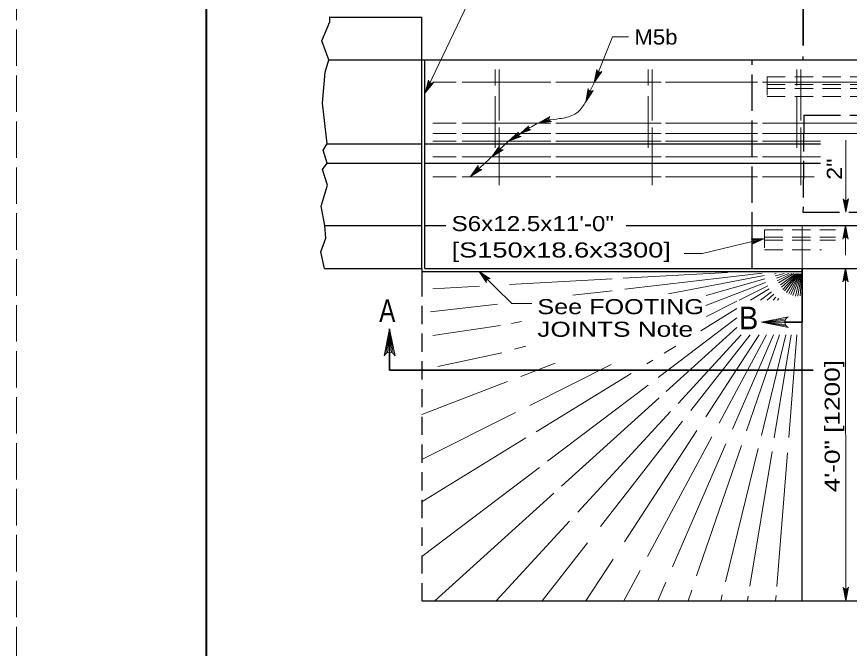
# Model space of a CAD drawing. Extents: x -1431.2 to -1397.2, y -1045.1 to -1001.1.
# Drawn here: x -1431.25 to -1422.47, y -1011.95 to -1005.3 of the extents above; entities that cross this region are included whole.
import ezdxf
from ezdxf.enums import TextEntityAlignment as Align

# ---------------------------------------------------------------- set-up
doc = ezdxf.new("R2010")
doc.units = 0
doc.header["$LTSCALE"] = 0.064
doc.linetypes.add('LONG_DASHED', pattern=[7.5, 6, -1.5])
doc.linetypes.add('MEDIUM_DASHED', pattern=[4.5, 3, -1.5])
doc.layers.add('1', color=7, linetype='Continuous', lineweight=13)

msp = doc.modelspace()

# ---------------------------------------------------------------- linework, layer by layer
at = {"layer": '1', "lineweight": 35}
for p, q in [((-1422.95608, -1005.60267), (-1422.95608, -1005.11975)), ((-1422.96592, -1007.95217), (-1422.96592, -1008.517)), ((-1423.08525, -1008.517), (-1423.15958, -1008.517)), ((-1422.96592, -1008.517), (-1423.08525, -1008.517)), ((-1427.31517, -1008.58883), (-1427.31517, -1009.0255)), ((-1422.84992, -1009.0255), (-1427.31517, -1009.0255))]:
    msp.add_line(p, q, dxfattribs=at)
at = {"layer": '1', "lineweight": 25}
for p, q in [((-1427.93092, -1005.30383), (-1426.97542, -1005.30383)), ((-1426.97542, -1007.86367), (-1426.97542, -1005.30083)), ((-1426.94317, -1007.86367), (-1426.94317, -1005.75617)), ((-1422.95608, -1005.75617), (-1422.95608, -1005.71917)), ((-1427.97375, -1006.64083), (-1426.97542, -1006.64083)), ((-1426.94317, -1006.64083), (-1422.77283, -1006.64083)), ((-1427.97375, -1006.84225), (-1426.97542, -1006.84225)), ((-1426.94317, -1006.84225), (-1422.77283, -1006.84225)), ((-1427.99758, -1007.49992), (-1426.97542, -1007.49992)), ((-1426.94317, -1007.49992), (-1426.723, -1007.49992)), ((-1424.82358, -1007.49992), (-1416.292, -1007.49992)), ((-1426.97542, -1007.95217), (-1426.97542, -1007.86367)), ((-1426.94317, -1007.95217), (-1426.94317, -1007.86367)), ((-1428.00233, -1007.95217), (-1426.97542, -1007.95217)), ((-1426.94317, -1007.95217), (-1422.96933, -1007.95242)), ((-1422.96592, -1011.455), (-1422.96592, -1007.95217)), ((-1422.96592, -1007.95217), (-1422.16017, -1007.95217)), ((-1426.97542, -1007.98392), (-1422.96933, -1007.98417)), ((-1426.97542, -1011.455), (-1410.98333, -1011.455))]:
    msp.add_line(p, q, dxfattribs=at)
at = {"layer": '1', "linetype": 'LONG_DASHED', "lineweight": 25}
for p, q in [((-1423.49433, -1007.745), (-1423.49433, -1005.75617)), ((-1422.94908, -1006.33642), (-1422.95892, -1007.36058)), ((-1423.49433, -1007.95217), (-1423.49433, -1007.745))]:
    msp.add_line(p, q, dxfattribs=at)
at = {"layer": '1'}
for p, q in [((-1426.20292, -1005.85733), (-1426.20292, -1006.02692)), ((-1426.16058, -1005.85733), (-1426.16058, -1006.39358)), ((-1424.58917, -1005.85733), (-1424.58917, -1006.02692)), ((-1424.54675, -1005.85733), (-1424.54675, -1006.39358)), ((-1423.02375, -1005.85733), (-1423.02375, -1006.02692)), ((-1422.98133, -1005.85733), (-1422.98133, -1006.39358)), ((-1425.12692, -1005.87125), (-1425.15825, -1005.99408)), ((-1425.1205, -1005.8785), (-1425.15825, -1005.99408)), ((-1425.11275, -1005.883), (-1425.15825, -1005.99408)), ((-1425.09208, -1005.88392), (-1425.15825, -1005.99408)), ((-1425.1015, -1005.88525), (-1425.15825, -1005.99408)), ((-1426.9005, -1005.98392), (-1426.94142, -1006.10392)), ((-1426.89467, -1005.99158), (-1426.94142, -1006.10392)), ((-1426.88733, -1005.99683), (-1426.94142, -1006.10392)), ((-1426.86683, -1005.99925), (-1426.94142, -1006.10392)), ((-1426.87625, -1005.99983), (-1426.94142, -1006.10392)), ((-1426.85817, -1005.99167), (-1426.61533, -1005.99167)), ((-1426.55142, -1005.99167), (-1425.61742, -1005.99167)), ((-1425.56242, -1005.99167), (-1424.45342, -1005.99167)), ((-1424.40625, -1005.99167), (-1423.43867, -1005.99167)), ((-1423.38433, -1005.99167), (-1422.26083, -1005.99167)), ((-1425.21833, -1006.07258), (-1425.24717, -1006.196)), ((-1425.21175, -1006.07967), (-1425.24717, -1006.196)), ((-1425.20392, -1006.08408), (-1425.24717, -1006.196)), ((-1425.18333, -1006.0845), (-1425.24717, -1006.196)), ((-1425.19258, -1006.086), (-1425.24717, -1006.196)), ((-1426.20292, -1006.139), (-1426.20292, -1006.68142)), ((-1424.58917, -1006.139), (-1424.58917, -1006.68142)), ((-1423.02375, -1006.139), (-1423.02375, -1006.68142)), ((-1425.63433, -1006.36725), (-1425.74867, -1006.42208)), ((-1425.63575, -1006.37683), (-1425.74867, -1006.42208)), ((-1425.63433, -1006.38567), (-1425.74867, -1006.42208)), ((-1426.85817, -1006.42175), (-1426.61533, -1006.42175)), ((-1426.55142, -1006.42175), (-1425.61742, -1006.42175)), ((-1426.16058, -1006.46925), (-1426.16058, -1007.07475)), ((-1425.85542, -1006.46475), (-1425.93567, -1006.53058)), ((-1425.85467, -1006.47267), (-1425.93567, -1006.53058)), ((-1425.62875, -1006.39575), (-1425.74867, -1006.42208)), ((-1425.62175, -1006.402), (-1425.74867, -1006.42208)), ((-1425.56242, -1006.42175), (-1424.45342, -1006.42175)), ((-1424.54675, -1006.46925), (-1424.54675, -1007.07475)), ((-1424.40625, -1006.42175), (-1423.43867, -1006.42175)), ((-1423.38433, -1006.42175), (-1422.289, -1006.42175)), ((-1422.98133, -1006.46925), (-1422.98133, -1007.07475)), ((-1426.85817, -1006.53208), (-1426.61533, -1006.53208)), ((-1426.55142, -1006.53208), (-1425.61742, -1006.53208)), ((-1425.96433, -1006.53175), (-1426.0625, -1006.612)), ((-1425.96342, -1006.54142), (-1426.0625, -1006.612)), ((-1425.95992, -1006.54967), (-1426.0625, -1006.612)), ((-1425.95217, -1006.55808), (-1426.0625, -1006.612)), ((-1425.94383, -1006.56258), (-1426.0625, -1006.612)), ((-1425.85183, -1006.47942), (-1425.93567, -1006.53058)), ((-1425.8455, -1006.48633), (-1425.93567, -1006.53058)), ((-1425.83867, -1006.48992), (-1425.93567, -1006.53058)), ((-1425.56242, -1006.53208), (-1424.45342, -1006.53208)), ((-1424.40625, -1006.53208), (-1423.43867, -1006.53208)), ((-1423.38433, -1006.53208), (-1422.289, -1006.53208)), ((-1426.85817, -1006.612), (-1426.61533, -1006.612)), ((-1426.55142, -1006.612), (-1425.61742, -1006.612)), ((-1426.0625, -1006.612), (-1426.46658, -1006.98617)), ((-1425.56242, -1006.612), (-1424.45342, -1006.612)), ((-1424.40625, -1006.612), (-1423.43867, -1006.612)), ((-1423.38433, -1006.612), (-1422.77283, -1006.612)), ((-1422.50817, -1006.60158), (-1422.50817, -1007.36058)), ((-1426.15917, -1006.67792), (-1426.23958, -1006.77592)), ((-1426.15642, -1006.68717), (-1426.23958, -1006.77592)), ((-1426.15133, -1006.69458), (-1426.23958, -1006.77592)), ((-1426.14208, -1006.70142), (-1426.23958, -1006.77592)), ((-1426.133, -1006.70417), (-1426.23958, -1006.77592)), ((-1426.85817, -1006.77592), (-1426.61533, -1006.77592)), ((-1426.55142, -1006.77592), (-1425.61742, -1006.77592)), ((-1425.56242, -1006.77592), (-1424.45342, -1006.77592)), ((-1424.40625, -1006.77592), (-1423.43867, -1006.77592)), ((-1423.38433, -1006.77592), (-1422.77283, -1006.77592)), ((-1426.3835, -1006.88525), (-1426.46392, -1006.98325)), ((-1426.38075, -1006.8945), (-1426.46392, -1006.98325)), ((-1426.37567, -1006.90192), (-1426.46392, -1006.98325)), ((-1426.36642, -1006.90867), (-1426.46392, -1006.98325)), ((-1426.35733, -1006.91142), (-1426.46392, -1006.98325)), ((-1426.85817, -1006.98883), (-1426.61533, -1006.98883)), ((-1426.55142, -1006.98883), (-1425.61742, -1006.98883)), ((-1425.56242, -1006.98883), (-1424.45342, -1006.98883)), ((-1424.40625, -1006.98883), (-1423.43867, -1006.98883)), ((-1423.38433, -1006.98883), (-1422.84142, -1006.98883)), ((-1422.52625, -1007.23125), (-1422.50817, -1007.36058)), ((-1422.51733, -1007.23558), (-1422.50817, -1007.36058)), ((-1422.48817, -1007.22967), (-1422.50817, -1007.36058)), ((-1422.49658, -1007.23467), (-1422.50817, -1007.36058)), ((-1422.50817, -1007.23692), (-1422.50817, -1007.36058)), ((-1422.96592, -1007.49992), (-1422.96592, -1007.95217)), ((-1422.53067, -1007.63075), (-1422.51067, -1007.49992)), ((-1422.52233, -1007.62583), (-1422.51067, -1007.49992)), ((-1422.51067, -1007.62358), (-1422.51067, -1007.49992)), ((-1422.50158, -1007.62492), (-1422.51067, -1007.49992)), ((-1423.49208, -1007.647), (-1423.36392, -1007.63725)), ((-1423.48558, -1007.65383), (-1423.36392, -1007.63725)), ((-1423.48225, -1007.68275), (-1423.36392, -1007.63725)), ((-1423.48083, -1007.66433), (-1423.36392, -1007.63725)), ((-1423.48008, -1007.67333), (-1423.36392, -1007.63725)), ((-1422.96592, -1007.95217), (-1422.98917, -1008.24208)), ((-1422.96592, -1007.95217), (-1422.97083, -1007.982)), ((-1422.96592, -1007.95217), (-1422.97025, -1007.96975)), ((-1422.96592, -1007.95217), (-1422.96992, -1007.96383)), ((-1422.96592, -1007.95217), (-1422.96975, -1007.96108)), ((-1422.96592, -1007.95217), (-1422.96967, -1007.95917)), ((-1422.96592, -1007.95217), (-1422.96958, -1007.95683)), ((-1422.96592, -1007.95217), (-1422.96958, -1007.95783)), ((-1422.96592, -1007.95217), (-1422.9695, -1007.95542)), ((-1422.96592, -1007.95217), (-1422.9695, -1007.95608)), ((-1422.96592, -1007.95217), (-1422.96942, -1007.95392)), ((-1422.96592, -1007.95217), (-1422.96942, -1007.95433)), ((-1422.96592, -1007.95217), (-1422.96942, -1007.95483)), ((-1422.96592, -1007.95217), (-1422.96942, -1007.9535)), ((-1422.96592, -1007.95217), (-1422.96933, -1007.95242)), ((-1422.96592, -1007.95217), (-1422.96933, -1007.95283)), ((-1422.96592, -1007.95217), (-1422.96933, -1007.95317)), ((-1422.96592, -1007.95217), (-1422.96933, -1007.95258)), ((-1422.53067, -1008.08167), (-1422.51067, -1007.95083)), ((-1422.52233, -1008.07675), (-1422.51067, -1007.95083)), ((-1422.51067, -1007.95083), (-1422.50817, -1011.455)), ((-1422.51067, -1008.0745), (-1422.51067, -1007.95083)), ((-1422.50158, -1008.07583), (-1422.51067, -1007.95083)), ((-1422.49258, -1008.08017), (-1422.51067, -1007.95083)), ((-1426.288, -1008.06875), (-1426.37292, -1007.984)), ((-1426.29442, -1008.07825), (-1426.37292, -1007.984)), ((-1426.29675, -1008.0875), (-1426.37292, -1007.984)), ((-1426.28075, -1008.06333), (-1426.37292, -1007.984)), ((-1426.27167, -1008.06017), (-1426.37292, -1007.984)), ((-1423.75267, -1007.99567), (-1424.85533, -1008.05667)), ((-1423.38983, -1008.00183), (-1424.83783, -1008.1715)), ((-1423.36767, -1008.02833), (-1424.377, -1008.21967)), ((-1423.24108, -1008.00433), (-1423.25967, -1008.00783)), ((-1423.15658, -1008.00575), (-1423.25092, -1008.03225)), ((-1423.10767, -1008.00658), (-1423.23675, -1008.05617)), ((-1423.07533, -1008.00717), (-1423.22975, -1008.08475)), ((-1423.056, -1008.0075), (-1423.21608, -1008.10558)), ((-1423.03933, -1008.00775), (-1423.19467, -1008.12525)), ((-1423.02758, -1008.00792), (-1423.18433, -1008.14975)), ((-1423.01742, -1008.00808), (-1423.17067, -1008.1745)), ((-1423.00975, -1008.00825), (-1423.15225, -1008.19017)), ((-1423.0025, -1008.00833), (-1423.13092, -1008.20567)), ((-1422.99617, -1008.0085), (-1423.1075, -1008.21583)), ((-1422.99042, -1008.00858), (-1423.08542, -1008.22708)), ((-1422.98533, -1008.00867), (-1423.06433, -1008.2385)), ((-1422.97975, -1008.00875), (-1423.03725, -1008.24308)), ((-1422.97525, -1008.00883), (-1423.01408, -1008.24383)), ((-1426.36767, -1008.14033), (-1426.86008, -1008.16758)), ((-1424.97042, -1008.06308), (-1426.05092, -1008.12283)), ((-1423.354, -1008.10108), (-1423.98425, -1008.343)), ((-1423.35958, -1008.06283), (-1423.98067, -1008.23725)), ((-1423.32892, -1008.1345), (-1423.63092, -1008.28617)), ((-1424.96892, -1008.18683), (-1425.38433, -1008.2355)), ((-1423.31417, -1008.16583), (-1423.51025, -1008.28617)), ((-1423.29125, -1008.19825), (-1423.40742, -1008.28617)), ((-1423.2655, -1008.22325), (-1423.33517, -1008.28617)), ((-1423.6545, -1008.298), (-1423.97458, -1008.45883)), ((-1423.24583, -1008.25608), (-1423.27358, -1008.28617)), ((-1423.21433, -1008.2695), (-1423.22742, -1008.28617)), ((-1426.17967, -1008.32867), (-1426.88517, -1008.41142)), ((-1423.6545, -1008.37467), (-1424.03583, -1008.60858)), ((-1423.6545, -1008.47308), (-1424.4835, -1009.10033)), ((-1423.138, -1008.4825), (-1423.39675, -1008.51875)), ((-1426.14583, -1008.55508), (-1426.86067, -1008.65817)), ((-1425.92533, -1008.51325), (-1426.03083, -1008.53325)), ((-1423.6545, -1008.575), (-1424.401, -1009.25017)), ((-1423.14675, -1008.50042), (-1423.39675, -1008.51875)), ((-1423.14942, -1008.51875), (-1423.39675, -1008.51875)), ((-1423.14483, -1008.542), (-1423.39675, -1008.51875)), ((-1423.13492, -1008.55875), (-1423.39675, -1008.51875)), ((-1427.35517, -1008.85067), (-1427.31517, -1008.58883)), ((-1427.33833, -1008.84075), (-1427.31517, -1008.58883)), ((-1427.31517, -1008.83617), (-1427.31517, -1008.58883)), ((-1427.29683, -1008.83883), (-1427.31517, -1008.58883)), ((-1427.27892, -1008.84758), (-1427.31517, -1008.58883)), ((-1423.61175, -1008.65325), (-1424.27575, -1009.37392)), ((-1423.51483, -1008.65325), (-1424.13933, -1009.45092)), ((-1423.42225, -1008.65325), (-1423.98283, -1009.51442)), ((-1423.34258, -1008.65325), (-1423.84158, -1009.58225)), ((-1423.27075, -1008.65325), (-1423.70233, -1009.64575)), ((-1423.207, -1008.65325), (-1423.554, -1009.66258)), ((-1423.13783, -1008.65325), (-1423.39758, -1009.71283)), ((-1423.08175, -1008.65325), (-1423.26083, -1009.73633)), ((-1423.02225, -1008.65325), (-1423.10883, -1009.73242)), ((-1426.13208, -1008.84158), (-1426.80608, -1008.98625)), ((-1425.87992, -1008.77075), (-1425.99967, -1008.80442)), ((-1424.30017, -1008.77075), (-1424.42067, -1008.84467)), ((-1424.54058, -1008.91825), (-1424.60542, -1008.958)), ((-1425.57033, -1008.95167), (-1425.93367, -1009.09108)), ((-1424.98042, -1008.964), (-1425.83858, -1009.39508)), ((-1424.769, -1009.05842), (-1425.77008, -1009.6725)), ((-1426.07292, -1009.1445), (-1426.97542, -1009.49083)), ((-1424.59025, -1009.18108), (-1425.65058, -1009.98325)), ((-1424.473, -1009.31525), (-1425.502, -1010.246)), ((-1425.98983, -1009.471), (-1426.97542, -1009.96608)), ((-1424.3555, -1009.46058), (-1425.33067, -1010.51908)), ((-1424.22733, -1009.56333), (-1425.09425, -1010.67058)), ((-1424.07675, -1009.65867), (-1424.84142, -1010.8335)), ((-1425.87783, -1009.73867), (-1426.97542, -1010.41208)), ((-1423.91925, -1009.72683), (-1424.59608, -1010.98667)), ((-1423.77025, -1009.802), (-1424.33233, -1011.09467)), ((-1423.60717, -1009.81717), (-1424.07967, -1011.19117)), ((-1423.43092, -1009.84858), (-1423.77533, -1011.25342)), ((-1423.285, -1009.8825), (-1423.51933, -1011.29975)), ((-1423.12208, -1009.89658), (-1423.235, -1011.30242)), ((-1425.73633, -1010.04817), (-1426.97542, -1010.98558)), ((-1425.58533, -1010.32133), (-1426.83875, -1011.455)), ((-1425.41867, -1010.61458), (-1426.19283, -1011.455)), ((-1425.23058, -1010.84467), (-1425.70842, -1011.455)), ((-1424.95933, -1011.01458), (-1425.246, -1011.455)), ((-1424.67558, -1011.13467), (-1424.84767, -1011.455)), ((-1424.40292, -1011.25683), (-1424.48908, -1011.455)), ((-1424.13158, -1011.34233), (-1424.17033, -1011.455)), ((-1422.52625, -1011.32567), (-1422.50817, -1011.455)), ((-1422.51733, -1011.33), (-1422.50817, -1011.455)), ((-1422.48817, -1011.32417), (-1422.50817, -1011.455)), ((-1422.49658, -1011.32908), (-1422.50817, -1011.455)), ((-1422.50817, -1011.33133), (-1422.50817, -1011.455)), ((-1423.80908, -1011.39117), (-1423.82475, -1011.455)), ((-1423.537, -1011.4065), (-1423.545, -1011.455)), ((-1423.24267, -1011.39817), (-1423.24725, -1011.455))]:
    msp.add_line(p, q, dxfattribs=at)
at = {"layer": '1', "linetype": 'MEDIUM_DASHED'}
for p, q in [((-1423.33717, -1005.93558), (-1423.33717, -1006.14133)), ((-1423.33717, -1005.93558), (-1416.27642, -1005.93558)), ((-1423.33717, -1006.01425), (-1416.27642, -1006.01425)), ((-1423.33717, -1006.056), (-1416.27642, -1006.056)), ((-1423.33717, -1006.14133), (-1416.27642, -1006.14133)), ((-1423.36392, -1007.5445), (-1423.36392, -1007.75642)), ((-1423.36392, -1007.5445), (-1422.6155, -1007.5445)), ((-1423.36392, -1007.6225), (-1422.6155, -1007.6225)), ((-1423.36392, -1007.65542), (-1422.6155, -1007.65542)), ((-1423.36392, -1007.75642), (-1422.76467, -1007.75642))]:
    msp.add_line(p, q, dxfattribs=at)
at = {"layer": '1', "linetype": 'LONG_DASHED'}
msp.add_lwpolyline([(-1431.24575, -1023.07983), (-1397.24575, -1023.07983), (-1397.24575, -1001.07983), (-1431.24575, -1001.07983)], close=True, dxfattribs=at)
at = {"layer": '1', "lineweight": 25}
for points in [[(-1397.74575, -1022.57983), (-1429.24575, -1022.57983), (-1429.24575, -1001.57983)], [(-1428.00233, -1007.95217), (-1428.0405, -1007.77617), (-1427.98808, -1007.63317), (-1427.99758, -1007.49992), (-1428.03567, -1007.29808), (-1427.969, -1007.07467), (-1428.02142, -1006.90933), (-1427.97375, -1006.84225), (-1428.01667, -1006.70825), (-1427.97375, -1006.64083), (-1428.02142, -1006.21233), (-1427.99283, -1005.88617), (-1427.95475, -1005.75617), (-1428.03092, -1005.5555), (-1427.94517, -1005.3545), (-1427.94517, -1005.30083), (-1427.93092, -1005.30383)], [(-1427.95475, -1005.75617), (-1426.94317, -1005.75617), (-1409.68083, -1005.75617)]]:
    msp.add_lwpolyline(points, dxfattribs=at)
at = {"layer": '1', "lineweight": 40}
msp.add_lwpolyline([(-1429.24575, -1001.57983), (-1397.74575, -1001.57983), (-1397.74575, -1022.57983), (-1429.24575, -1022.57983)], close=True, dxfattribs=at)
at = {"layer": '1'}
for points in [[(-1426.94142, -1006.10392), (-1426.15542, -1004.45958), (-1425.89817, -1004.45958)], [(-1425.16217, -1006.00292), (-1424.96517, -1005.51192), (-1424.79842, -1005.51192)], [(-1425.08, -1005.87625), (-1425.15825, -1005.99408), (-1425.13133, -1005.85525)], [(-1426.85417, -1005.99258), (-1426.94142, -1006.10392), (-1426.90367, -1005.96758)], [(-1425.17133, -1006.07667), (-1425.24717, -1006.196), (-1425.22308, -1006.05667)], [(-1425.60808, -1006.40642), (-1425.74867, -1006.42208), (-1425.62492, -1006.35358)], [(-1425.827, -1006.49083), (-1425.93567, -1006.53058), (-1425.85058, -1006.45208)], [(-1425.92958, -1006.56358), (-1426.0625, -1006.612), (-1425.95842, -1006.51625)], [(-1426.11883, -1006.70233), (-1426.23958, -1006.77592), (-1426.15642, -1006.66158)], [(-1426.34317, -1006.90958), (-1426.46392, -1006.98325), (-1426.38075, -1006.86883)], [(-1422.47958, -1007.21767), (-1422.50817, -1007.36058), (-1422.53675, -1007.21767)], [(-1422.53925, -1007.64275), (-1422.51067, -1007.49992), (-1422.48208, -1007.64275)], [(-1422.49258, -1007.62925), (-1422.51067, -1007.49992), (-1422.51067, -1007.8145)], [(-1423.36392, -1007.63725), (-1424.0185, -1007.79533), (-1424.20925, -1007.79533)], [(-1423.50525, -1007.6415), (-1423.36392, -1007.63725), (-1423.49275, -1007.69558)], [(-1422.53925, -1008.09367), (-1422.51067, -1007.95083), (-1422.48208, -1008.09367)], [(-1426.37292, -1007.984), (-1426.02858, -1008.32083), (-1425.81467, -1008.32083)], [(-1426.29433, -1008.10158), (-1426.37292, -1007.984), (-1426.25517, -1008.06225)], [(-1423.11092, -1008.57583), (-1423.39675, -1008.51875), (-1423.11092, -1008.46158)], [(-1427.37225, -1008.87467), (-1427.31517, -1008.58883), (-1427.258, -1008.87467)], [(-1422.47958, -1011.31208), (-1422.50817, -1011.455), (-1422.53675, -1011.31208)]]:
    msp.add_lwpolyline(points, dxfattribs=at)
at = {"layer": '1', "linetype": 'LONG_DASHED', "lineweight": 25}
for points in [[(-1422.94908, -1006.33642), (-1416.01508, -1006.33642), (-1414.94533, -1006.33642)], [(-1422.95892, -1007.36058), (-1416.0495, -1007.36058), (-1414.95508, -1007.36058)]]:
    msp.add_lwpolyline(points, dxfattribs=at)
at = {"layer": '1', "linetype": 'MEDIUM_DASHED', "lineweight": 25}
msp.add_lwpolyline([(-1426.97542, -1007.95217), (-1426.97542, -1008.05525), (-1426.97542, -1011.455)], dxfattribs=at)
at = {"layer": '1'}
for centre, radius, start, end in [((-1422.50822, -1007.20616), 0.03084, 202.08782, 337.91395), ((-1422.51064, -1007.65434), 0.03084, 22.08782, 157.91395), ((-1422.51065, -1008.10526), 0.03084, 22.08782, 157.91395), ((-1423.08787, -1008.51865), 0.06168, 112.08782, 247.91395), ((-1427.31506, -1008.89772), 0.06168, 22.08782, 157.91395), ((-1422.50822, -1011.30058), 0.03084, 202.08782, 337.91395)]:
    msp.add_arc(centre, radius, start, end, dxfattribs=at)
for centre, major_axis, start_param, end_param in [((-1425.10143, -1005.85535), (-0.02984, -0.00239), 6.2002697, 8.5708828), ((-1426.87386, -1005.97005), (-0.00811, -0.02881), 4.9044669, 7.27508), ((-1425.19317, -1006.05615), (-0.02875, -0.00833), 6.0186602, 8.3892733), ((-1425.60578, -1006.37656), (-0.02932, 0.00601), 5.6086732, 7.9792863), ((-1425.83093, -1006.46664), (-0.02449, 0), 5.6459012, 8.0165144), ((-1425.93437, -1006.53411), (-0.02935, 0.0059), 5.8425909, 8.213204), ((-1426.12933, -1006.67433), (-0.02993, 0), 5.8425909, 8.213204), ((-1426.35366, -1006.88162), (-0.02993, 0), 5.8425909, 8.213204), ((-1423.50999, -1007.67109), (0.02993, 0), 5.3254679, 7.6960811), ((-1426.26678, -1008.08988), (0.01827, 0.02371), 0.2575274, 2.6281405)]:
    msp.add_ellipse(centre, major_axis=major_axis, ratio=0.999895, start_param=start_param, end_param=end_param, dxfattribs=at)
for points in [[(-1425.24825, -1006.19683), (-1425.22567, -1006.13317), (-1425.18492, -1006.04792), (-1425.1565, -1005.99167)], [(-1425.748, -1006.42175), (-1425.65367, -1006.39317), (-1425.52425, -1006.37425), (-1425.37758, -1006.3345), (-1425.32925, -1006.30342), (-1425.24825, -1006.19683)], [(-1425.93325, -1006.53208), (-1425.88883, -1006.50067), (-1425.748, -1006.42175)], [(-1426.0625, -1006.612), (-1426.0085, -1006.578), (-1425.93325, -1006.53208)]]:
    msp.add_spline(points, degree=3, dxfattribs=at)

# ---------------------------------------------------------------- texts
for s, height, width, p in [('M5b', 0.1588, 1.1, (-1424.73567, -1005.594)), ('S6x12.5x11\'-0"', 0.1588, 1.2, (-1426.66217, -1007.55967)), ('[S150x18.6x3300]', 0.1588, 1.35, (-1426.66217, -1007.8375)), ('A', 0.2382, 0.8, (-1427.42458, -1008.51658)), ('See FOOTING', 0.1588, 1.25, (-1425.75833, -1008.4345)), ('B', 0.2382, 0.95, (-1423.63183, -1008.59367)), ('JOINTS Note', 0.1588, 1.3, (-1425.75833, -1008.67267))]:
    msp.add_text(s, height=height, dxfattribs=dict(at, width=width)).set_placement(p)
for s, width, p in [('2"', 1.15, (-1422.54875, -1006.90675)), ('4\'-0" [1200]', 1.3, (-1422.57125, -1009.61417))]:
    msp.add_text(s, height=0.1588, rotation=90, dxfattribs=dict(at, width=width)).set_placement(p, align=Align.CENTER)

doc.saveas('drawing.dxf')
